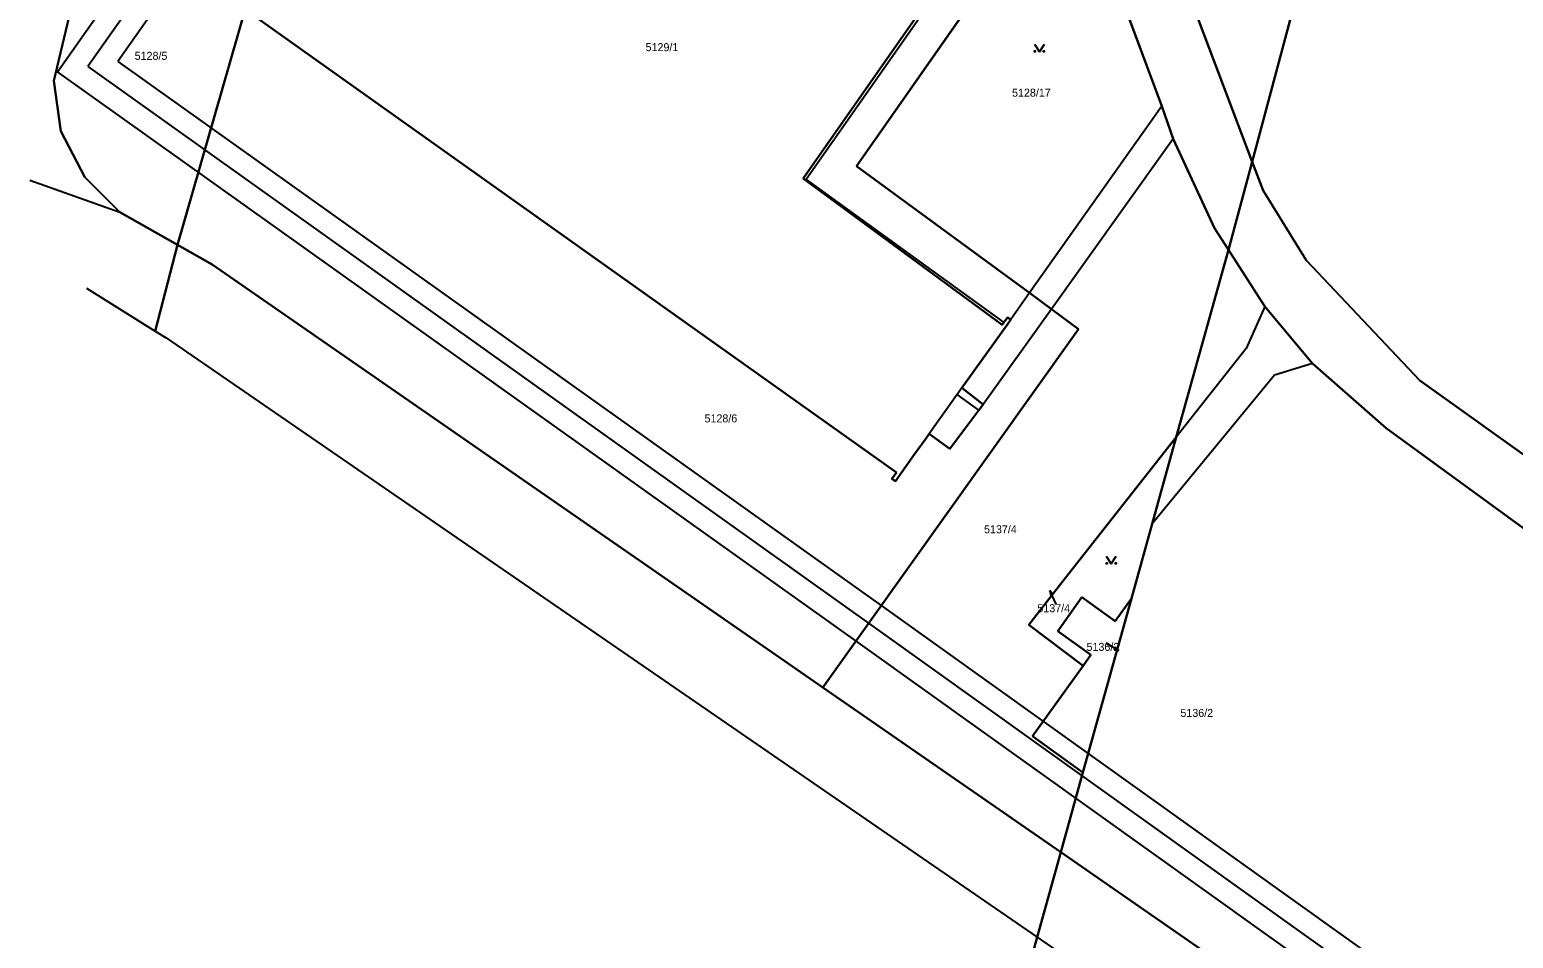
# Model space of a CAD drawing. Extents: x -400488 to -400124, y -1251493 to -1251223.
# Drawn here: x -400486.9 to -400397.9, y -1251353.8 to -1251299.4 of the extents above; entities that cross this region are included whole.
import ezdxf

# ---------------------------------------------------------------- set-up
doc = ezdxf.new("R2010")
doc.units = 0
doc.layers.add('Level 63', color=7, linetype='Continuous')

msp = doc.modelspace()

# ---------------------------------------------------------------- linework, layer by layer
at = {"layer": 'Level 63'}
for p, q in [((-400485.24, -1251301.87), (-400474.08, -1251285.99)), ((-400473.73, -1251287.79), (-400483.43, -1251301.56)), ((-400420.65, -1251288.62), (-400413.58, -1251307.27)), ((-400413.58, -1251307.27), (-400420.65, -1251288.62)), ((-400408.63, -1251288.78), (-400413.58, -1251307.27)), ((-400413.58, -1251307.27), (-400408.63, -1251288.78)), ((-400473.44, -1251289.61), (-400481.62, -1251301.25)), ((-400418.99, -1251303.93), (-400423.92, -1251290.71)), ((-400423.92, -1251290.71), (-400418.99, -1251303.93)), ((-400426.97, -1251292.77), (-400437.31, -1251307.53)), ((-400437.31, -1251307.53), (-400426.97, -1251292.77)), ((-400440.52, -1251308.27), (-400430.11, -1251293.41)), ((-400430.11, -1251293.41), (-400440.52, -1251308.27)), ((-400429.94, -1251293.53), (-400440.34, -1251308.34)), ((-400485.47, -1251302.42), (-400484.54, -1251298.57)), ((-400484.54, -1251298.57), (-400485.47, -1251302.42)), ((-400473.99, -1251298.15), (-400478.04, -1251312.25)), ((-400478.04, -1251312.25), (-400473.99, -1251298.15)), ((-400473.99, -1251298.15), (-400434.92, -1251325.91)), ((-400434.92, -1251325.91), (-400473.99, -1251298.15)), ((-400426.64, -1251300.23), (-400426.34, -1251300.68)), ((-400426.34, -1251300.68), (-400426.04, -1251300.23)), ((-400481.62, -1251301.25), (-400435.27, -1251334.27)), ((-400436.79, -1251336.39), (-400485.24, -1251301.87)), ((-400483.43, -1251301.56), (-400436.03, -1251335.33)), ((-400485.05, -1251305.43), (-400485.47, -1251302.42)), ((-400485.47, -1251302.42), (-400485.05, -1251305.43)), ((-400418.99, -1251303.93), (-400426.93, -1251315.14)), ((-400418.32, -1251305.9), (-400418.99, -1251303.93)), ((-400418.99, -1251303.93), (-400418.32, -1251305.9)), ((-400483.6, -1251308.19), (-400485.05, -1251305.43)), ((-400485.05, -1251305.43), (-400483.6, -1251308.19)), ((-400418.32, -1251305.9), (-400425.61, -1251316.11)), ((-400415.84, -1251311.26), (-400418.32, -1251305.9)), ((-400418.32, -1251305.9), (-400415.84, -1251311.26)), ((-400437.31, -1251307.53), (-400426.93, -1251315.14)), ((-400426.93, -1251315.14), (-400437.31, -1251307.53)), ((-400413.58, -1251307.27), (-400415.01, -1251312.55)), ((-400415.01, -1251312.55), (-400413.58, -1251307.27)), ((-400413.58, -1251307.27), (-400412.92, -1251309)), ((-400412.92, -1251309), (-400413.58, -1251307.27)), ((-400486.91, -1251308.38), (-400481.51, -1251310.29)), ((-400481.51, -1251310.29), (-400483.6, -1251308.19)), ((-400483.6, -1251308.19), (-400481.51, -1251310.29)), ((-400428.57, -1251317.04), (-400440.52, -1251308.27)), ((-400440.52, -1251308.27), (-400428.57, -1251317.04)), ((-400440.34, -1251308.34), (-400428.47, -1251316.9)), ((-400412.92, -1251309), (-400410.34, -1251313.18)), ((-400410.34, -1251313.18), (-400412.92, -1251309)), ((-400478.04, -1251312.25), (-400481.51, -1251310.29)), ((-400481.51, -1251310.29), (-400478.04, -1251312.25)), ((-400415.01, -1251312.55), (-400415.84, -1251311.26)), ((-400415.84, -1251311.26), (-400415.01, -1251312.55)), ((-400478.04, -1251312.25), (-400479.38, -1251317.43)), ((-400479.38, -1251317.43), (-400478.04, -1251312.25)), ((-400475.96, -1251313.43), (-400478.04, -1251312.25)), ((-400478.04, -1251312.25), (-400475.96, -1251313.43)), ((-400415.01, -1251312.55), (-400418.13, -1251323.78)), ((-400418.13, -1251323.78), (-400415.01, -1251312.55)), ((-400415.01, -1251312.55), (-400412.83, -1251315.95)), ((-400412.83, -1251315.95), (-400415.01, -1251312.55)), ((-400439.34, -1251338.79), (-400475.96, -1251313.43)), ((-400475.96, -1251313.43), (-400439.34, -1251338.79)), ((-400410.34, -1251313.18), (-400403.53, -1251320.38)), ((-400403.53, -1251320.38), (-400410.34, -1251313.18)), ((-400483.51, -1251314.86), (-400479.38, -1251317.43)), ((-400426.93, -1251315.14), (-400428.05, -1251316.72)), ((-400426.93, -1251315.14), (-400425.61, -1251316.11)), ((-400425.61, -1251316.11), (-400426.93, -1251315.14)), ((-400425.61, -1251316.11), (-400429.72, -1251321.83)), ((-400425.61, -1251316.11), (-400423.99, -1251317.3)), ((-400423.99, -1251317.3), (-400425.61, -1251316.11)), ((-400412.83, -1251315.95), (-400413.94, -1251318.46)), ((-400412.83, -1251315.95), (-400409.96, -1251319.37)), ((-400409.96, -1251319.37), (-400412.83, -1251315.95)), ((-400423.99, -1251317.3), (-400439.34, -1251338.79)), ((-400439.34, -1251338.79), (-400423.99, -1251317.3)), ((-400430.99, -1251320.82), (-400428.28, -1251317.04)), ((-400428.28, -1251317.04), (-400430.99, -1251320.82)), ((-400428.47, -1251316.9), (-400428.57, -1251317.04)), ((-400428.57, -1251317.04), (-400428.47, -1251316.9)), ((-400428.26, -1251316.61), (-400428.47, -1251316.9)), ((-400428.47, -1251316.9), (-400428.26, -1251316.61)), ((-400428.28, -1251317.04), (-400428.05, -1251316.72)), ((-400428.05, -1251316.72), (-400428.28, -1251317.04)), ((-400428.05, -1251316.72), (-400428.26, -1251316.61)), ((-400428.26, -1251316.61), (-400428.05, -1251316.72)), ((-400479.38, -1251317.43), (-400478.73, -1251317.83)), ((-400478.73, -1251317.83), (-400426.48, -1251353.77)), ((-400413.94, -1251318.46), (-400418.13, -1251323.78)), ((-400409.96, -1251319.37), (-400412.24, -1251320.07)), ((-400409.96, -1251319.37), (-400405.54, -1251323.24)), ((-400405.54, -1251323.24), (-400409.96, -1251319.37)), ((-400430.99, -1251320.82), (-400431.28, -1251321.23)), ((-400429.72, -1251321.83), (-400430.99, -1251320.82)), ((-400430.99, -1251320.82), (-400429.72, -1251321.83)), ((-400412.24, -1251320.07), (-400419.58, -1251328.98)), ((-400403.53, -1251320.38), (-400393.06, -1251327.88)), ((-400393.06, -1251327.88), (-400403.53, -1251320.38)), ((-400431.28, -1251321.23), (-400432.95, -1251323.58)), ((-400429.97, -1251322.17), (-400431.28, -1251321.23)), ((-400431.72, -1251324.48), (-400429.97, -1251322.17)), ((-400429.97, -1251322.17), (-400431.72, -1251324.48)), ((-400429.97, -1251322.17), (-400429.72, -1251321.83)), ((-400429.72, -1251321.83), (-400429.97, -1251322.17)), ((-400433.18, -1251323.9), (-400432.95, -1251323.58)), ((-400432.95, -1251323.58), (-400433.18, -1251323.9)), ((-400432.95, -1251323.58), (-400431.72, -1251324.48)), ((-400431.72, -1251324.48), (-400432.95, -1251323.58)), ((-400405.54, -1251323.24), (-400382.17, -1251340.28)), ((-400382.17, -1251340.28), (-400405.54, -1251323.24)), ((-400433.83, -1251324.81), (-400433.18, -1251323.9)), ((-400433.18, -1251323.9), (-400433.83, -1251324.81)), ((-400418.13, -1251323.78), (-400424.85, -1251332.32)), ((-400424.85, -1251332.32), (-400418.13, -1251323.78)), ((-400418.13, -1251323.78), (-400419.58, -1251328.98)), ((-400419.58, -1251328.98), (-400418.13, -1251323.78)), ((-400434.98, -1251326.42), (-400433.83, -1251324.81)), ((-400433.83, -1251324.81), (-400434.98, -1251326.42)), ((-400434.92, -1251325.91), (-400435.19, -1251326.28)), ((-400435.19, -1251326.28), (-400434.92, -1251325.91)), ((-400435.19, -1251326.28), (-400434.98, -1251326.42)), ((-400434.98, -1251326.42), (-400435.19, -1251326.28)), ((-400419.58, -1251328.98), (-400420.82, -1251333.45)), ((-400420.82, -1251333.45), (-400419.58, -1251328.98)), ((-400422.33, -1251330.93), (-400422.03, -1251331.38)), ((-400422.03, -1251331.38), (-400421.73, -1251330.93)), ((-400424.85, -1251332.32), (-400426.98, -1251335.03)), ((-400426.98, -1251335.03), (-400424.85, -1251332.32)), ((-400425.34, -1251333.8), (-400425.721, -1251332.984)), ((-400425.721, -1251332.984), (-400425.648, -1251333.282)), ((-400425.539, -1251333.231), (-400425.721, -1251332.984)), ((-400425.24, -1251335.42), (-400423.79, -1251333.38)), ((-400423.79, -1251333.38), (-400425.24, -1251335.42)), ((-400423.79, -1251333.38), (-400421.8, -1251334.81)), ((-400421.8, -1251334.81), (-400423.79, -1251333.38)), ((-400420.82, -1251333.45), (-400423.73, -1251343.9)), ((-400423.73, -1251343.9), (-400420.82, -1251333.45)), ((-400421.8, -1251334.81), (-400420.82, -1251333.45)), ((-400420.82, -1251333.45), (-400421.8, -1251334.81)), ((-400435.27, -1251334.27), (-400389.79, -1251366.78)), ((-400426.98, -1251335.03), (-400423.72, -1251337.49)), ((-400423.72, -1251337.49), (-400426.98, -1251335.03)), ((-400436.03, -1251335.33), (-400389.43, -1251368.65)), ((-400423.25, -1251336.84), (-400425.24, -1251335.42)), ((-400425.24, -1251335.42), (-400423.25, -1251336.84)), ((-400391.27, -1251368.93), (-400436.79, -1251336.39)), ((-400423.72, -1251337.49), (-400423.25, -1251336.84)), ((-400423.25, -1251336.84), (-400423.72, -1251337.49)), ((-400422.36, -1251336.12), (-400421.581, -1251336.571)), ((-400421.871, -1251336.472), (-400421.581, -1251336.571)), ((-400421.581, -1251336.571), (-400421.811, -1251336.369)), ((-400423.72, -1251337.49), (-400426.75, -1251341.72)), ((-400426.75, -1251341.72), (-400423.72, -1251337.49)), ((-400425.06, -1251348.67), (-400439.34, -1251338.79)), ((-400439.34, -1251338.79), (-400425.06, -1251348.67)), ((-400426.75, -1251341.72), (-400423.73, -1251343.9)), ((-400423.73, -1251343.9), (-400426.75, -1251341.72)), ((-400423.73, -1251343.9), (-400425.06, -1251348.67)), ((-400425.06, -1251348.67), (-400423.73, -1251343.9)), ((-400425.06, -1251348.67), (-400426.48, -1251353.77)), ((-400426.48, -1251353.77), (-400425.06, -1251348.67)), ((-400413.07, -1251356.97), (-400425.06, -1251348.67)), ((-400425.06, -1251348.67), (-400413.07, -1251356.97)), ((-400426.48, -1251353.77), (-400437.67, -1251393.84)), ((-400437.67, -1251393.84), (-400426.48, -1251353.77)), ((-400426.48, -1251353.77), (-400416.37, -1251360.72)), ((-400426.48, -1251353.77), (-400416.37, -1251360.72))]:
    msp.add_line(p, q, dxfattribs=at)
for centre in [(-400426.61, -1251300.65), (-400426.07, -1251300.65), (-400422.3, -1251331.35), (-400421.76, -1251331.35)]:
    msp.add_circle(centre, 0.03, dxfattribs=at)

# ---------------------------------------------------------------- texts
for s, p in [('5129/1', (-400449.964, -1251300.64)), ('5128/5', (-400480.612, -1251301.16)), ('5128/17', (-400427.984, -1251303.37)), ('5128/6', (-400446.43, -1251322.9)), ('5137/4', (-400429.664, -1251329.55)), ('5137/4', (-400426.464, -1251334.28)), ('5136/2', (-400423.516, -1251336.6)), ('5136/2', (-400417.886, -1251340.56))]:
    msp.add_text(s, height=0.48, dxfattribs=at).set_placement(p)

doc.saveas('drawing.dxf')
